// Mitsubishi GX Works2 project: 台达变频器通讯   PLC: FX3U/FX3UC

PROGRAM MAIN
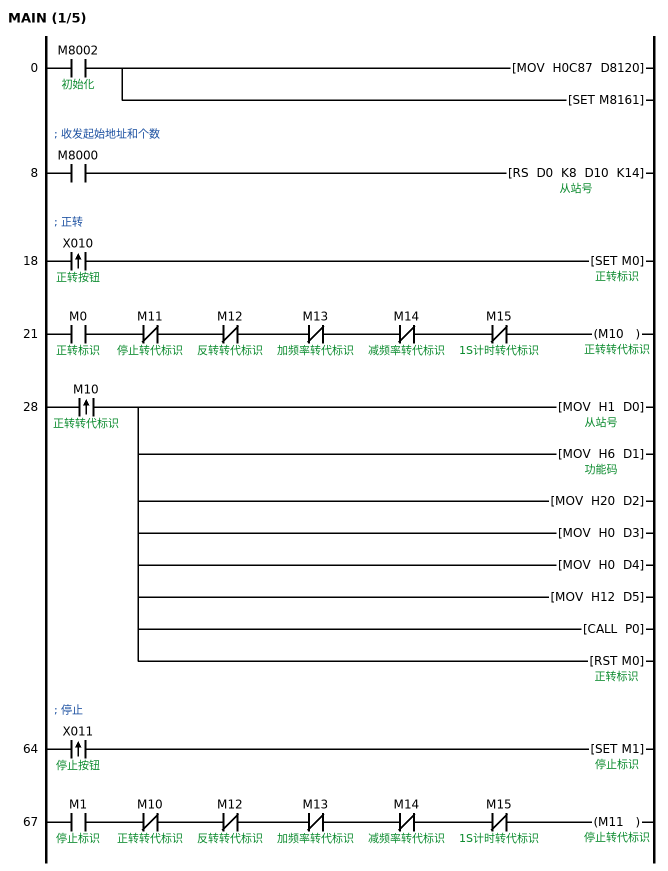
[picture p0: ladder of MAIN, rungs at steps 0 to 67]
0     LD      M8002  ; 初始化
      MOV     H0C87 D8120
        [note] 通讯格式
      SET     M8161
        [note] 指定数据处理模式为8位
; 收发起始地址和个数
8     LD      M8000
      RS      D0 K8 D10 K14  ; 从站号
        [note] 发收数据的起始地址
; 正转
18    LDP     X010  ; 正转按钮
      SET     M0  ; 正转标识
21    LD      M0  ; 正转标识
      ANI     M11  ; 停止转代标识
      ANI     M12  ; 反转转代标识
      ANI     M13  ; 加频率转代标识
      ANI     M14  ; 减频率转代标识
      ANI     M15  ; 1S计时转代标识
      OUT     M10  ; 正转转代标识
28    LDP     M10  ; 正转转代标识
      MOV     H1 D0
        [note] 从站站号
      MOV     H6 D1  ; 功能码
        [note] 功能码：发送
      MOV     H20 D2
        [note] 写入命令地址的高八位
      MOV     H0 D3
        [note] 写入命令地址的低八位
      MOV     H0 D4
        [note] 写入数据启动正转  高八位
      MOV     H12 D5
        [note] 写入数据启动正转  低八位
      CALL    P0
        [note] CRC校验
      RST     M0  ; 正转标识
; 停止
64    LDP     X011  ; 停止按钮
      SET     M1  ; 停止标识
67    LD      M1  ; 停止标识
      ANI     M10  ; 正转转代标识
      ANI     M12  ; 反转转代标识
      ANI     M13  ; 加频率转代标识
      ANI     M14  ; 减频率转代标识
      ANI     M15  ; 1S计时转代标识
      OUT     M11  ; 停止转代标识
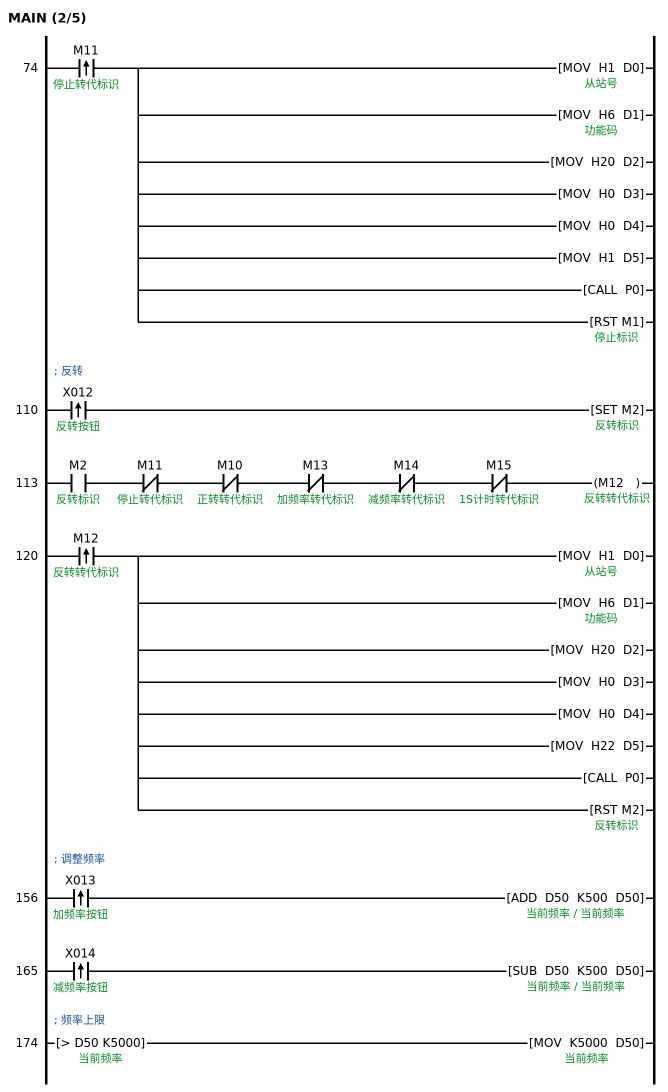
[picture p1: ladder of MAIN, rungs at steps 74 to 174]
74    LDP     M11  ; 停止转代标识
      MOV     H1 D0
        [note] 从站站号
      MOV     H6 D1
        [note] 功能码：发送
      MOV     H20 D2
        [note] 写入命令地址的高八位
      MOV     H0 D3
        [note] 写入命令地址的低八位
      MOV     H0 D4
        [note] 写入停止命令的高八位
      MOV     H1 D5
        [note] 写入停止命令的低八位
      CALL    P0
        [note] CRC校验
      RST     M1  ; 停止标识
; 反转
110   LDP     X012  ; 反转按钮
      SET     M2  ; 反转标识
113   LD      M2  ; 反转标识
      ANI     M11  ; 停止转代标识
      ANI     M10  ; 正转转代标识
      ANI     M13  ; 加频率转代标识
      ANI     M14  ; 减频率转代标识
      ANI     M15  ; 1S计时转代标识
      OUT     M12  ; 反转转代标识
120   LDP     M12  ; 反转转代标识
      MOV     H1 D0
        [note] 从站站号
      MOV     H6 D1
        [note] 功能码：发送
      MOV     H20 D2
        [note] 写入命令地址的高八位
      MOV     H0 D3
        [note] 写入命令地址的低八位
      MOV     H0 D4
        [note] 写入反转命令的高八位
      MOV     H22 D5
        [note] 写入反转命令的低八位
      CALL    P0
        [note] CRC校验
      RST     M2  ; 反转标识
; 调整频率
156   LDP     X013  ; 加频率按钮
      ADD     D50 K500 D50  ; 当前频率
        [note] 加频率
165   LDP     X014  ; 减频率按钮
      SUB     D50 K500 D50
        [note] 减频率
; 频率上限
174   LD>     D50 K5000  ; 当前频率
      MOV     K5000 D50
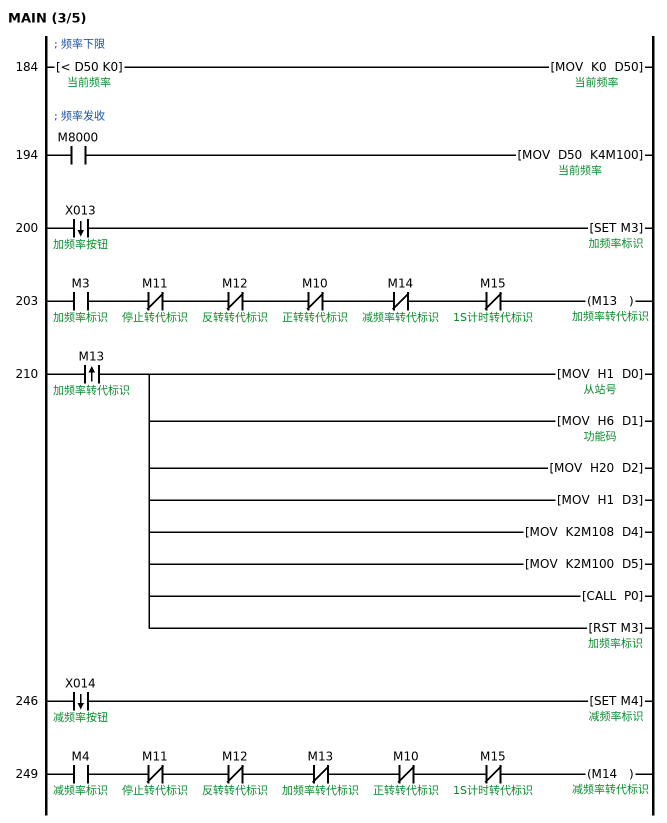
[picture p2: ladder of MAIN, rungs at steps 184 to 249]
; 频率下限
184   LD<     D50 K0  ; 当前频率
      MOV     K0 D50
; 频率发收
194   LD      M8000
      MOV     D50 K4M100
        [note] 将D50传到16个位里
200   LDF     X013  ; 加频率按钮
      SET     M3  ; 加频率标识
203   LD      M3  ; 加频率标识
      ANI     M11  ; 停止转代标识
      ANI     M12  ; 反转转代标识
      ANI     M10  ; 正转转代标识
      ANI     M14  ; 减频率转代标识
      ANI     M15  ; 1S计时转代标识
      OUT     M13  ; 加频率转代标识
210   LDP     M13  ; 加频率转代标识
      MOV     H1 D0
        [note] 从站站号
      MOV     H6 D1
        [note] 功能码：发送
      MOV     H20 D2
        [note] 加频率命令地址的高八位
      MOV     H1 D3
        [note] 加频率命令地址的低八位
      MOV     K2M108 D4
        [note] 写入加频率频率命令地址的高八位
      MOV     K2M100 D5
        [note] 写入加频率频率命令地址的低八位
      CALL    P0
        [note] CRC校验
      RST     M3  ; 加频率标识
246   LDF     X014  ; 减频率按钮
      SET     M4  ; 减频率标识
249   LD      M4  ; 减频率标识
      ANI     M11  ; 停止转代标识
      ANI     M12  ; 反转转代标识
      ANI     M13  ; 加频率转代标识
      ANI     M10  ; 正转转代标识
      ANI     M15  ; 1S计时转代标识
      OUT     M14  ; 减频率转代标识
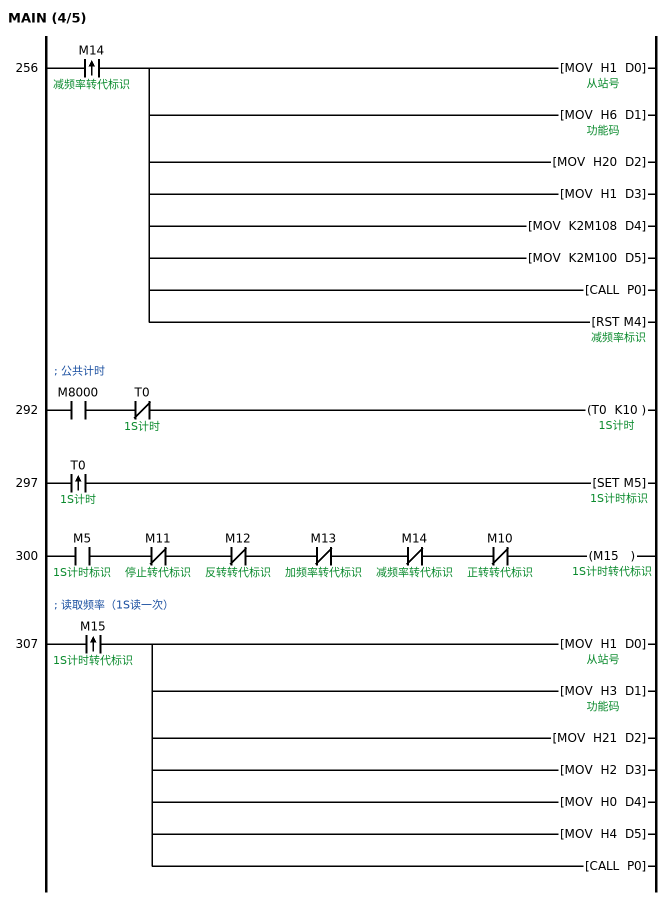
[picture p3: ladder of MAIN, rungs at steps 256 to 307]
256   LDP     M14  ; 减频率转代标识
      MOV     H1 D0
        [note] 从站站号
      MOV     H6 D1
        [note] 功能码：发送
      MOV     H20 D2
        [note] 减频率命令地址的高八位
      MOV     H1 D3
        [note] 减频率命令地址的低八位
      MOV     K2M108 D4
        [note] 写入减频率命令地址的高八位
      MOV     K2M100 D5
        [note] 写入减频率命令地址的低八位
      CALL    P0
        [note] CRC校验
      RST     M4  ; 减频率标识
; 公共计时
292   LD      M8000
      ANI     T0  ; 1S计时
      OUT     T0 K10  ; 1S计时
297   LDP     T0  ; 1S计时
      SET     M5  ; 1S计时标识
300   LD      M5  ; 1S计时标识
      ANI     M11  ; 停止转代标识
      ANI     M12  ; 反转转代标识
      ANI     M13  ; 加频率转代标识
      ANI     M14  ; 减频率转代标识
      ANI     M10  ; 正转转代标识
      OUT     M15  ; 1S计时转代标识
; 读取频率（1S读一次）
307   LDP     M15  ; 1S计时转代标识
      MOV     H1 D0
        [note] 从站站号
      MOV     H3 D1
        [note] 功能码：读取
      MOV     H21 D2
        [note] 读频率命令地址的高八位
      MOV     H2 D3
        [note] 读频率命令地址的低八位
      MOV     H0 D4
        [note] 写入读频率命令地址的高八位
      MOV     H4 D5
        [note] 写入读频率命令地址的低八位
      CALL    P0
        [note] CRC校验
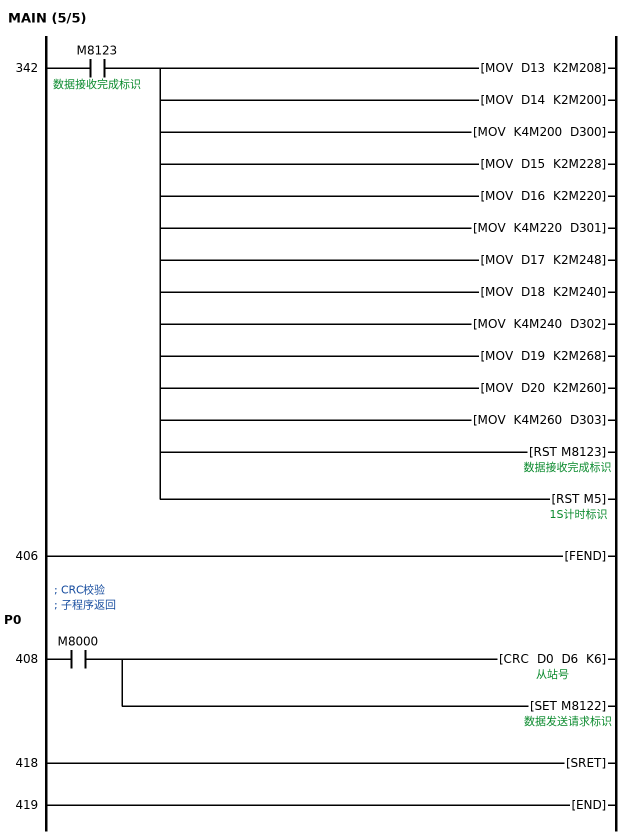
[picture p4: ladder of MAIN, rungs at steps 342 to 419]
342   LD      M8123  ; 数据接收完成标识
      MOV     D13 K2M208
        [note] 接收频率命令地址的高八位
      MOV     D14 K2M200
        [note] 接收频率命令地址的低八位
      MOV     K4M200 D300
        [note] 把接收频率高低八位组合，传到D300
      MOV     D15 K2M228
        [note] 输出频率命令高八位
      MOV     D16 K2M220
        [note] 输出频率命令低八位
      MOV     K4M220 D301
      MOV     D17 K2M248
        [note] 输出电流命令高八位
      MOV     D18 K2M240
        [note] 输出电流命令低八位
      MOV     K4M240 D302
      MOV     D19 K2M268
        [note] 输出电压命令高八位
      MOV     D20 K2M260
        [note] 输出电压命令低八位
      MOV     K4M260 D303
      RST     M8123  ; 数据接收完成标识
      RST     M5  ; 1S计时标识
406   FEND
; CRC校验
      P0
408   LD      M8000
      CRC     D0 D6 K6
      SET     M8122  ; 数据发送请求标识
; 子程序返回
418   SRET
419   END
END_PROGRAM
